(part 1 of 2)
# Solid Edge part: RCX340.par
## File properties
Title: RCX340
Author: psadmin
Template: iso metric part.par
Last saved by: psadmin
Revision: 1
Application: Solid Edge
Document Number: RCX340
Company: YAMAHA
Accuracy: 0,990
NB: RCX340
NN: RCX340
NBSYN: $TYPE.
LINA: RCX340
CATALOG: Yamaha
TYPE: RCX340
SUPPLIER: YAMAHA
ARTICLENO: RCX340
BOMINFO: RCX340
CREATOR: CADENAS GmbH
ID: yamaha:RCX340
CADENASIDSTR: DOCATTR{IDENT{"{$CADENAS_DATA\\23d-libs\\yamaha\\controller\\rcx340\\rcx340.prj},152 {VTYP=3D},{NB=RCX340},{LINA=RCX340},{NN=RCX340},{DATE=25.08.2021 00:08:20},{GEOMDATE=17.03.2021 09:07:48},{VERSION=},{LINEID=20},{WBVAR=},{WBNUMERIC=}  {NB=RCX340},{LINA=RCX340},{KT=DUMMY},{TYPE=RCX340},{VERS=1},{VER=1}"}}
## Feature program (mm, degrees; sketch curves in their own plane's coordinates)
sketch for "ExtrudedProtrusion_1" plane through (0, 0, 0) normal (1, 0, 0) x-axis (0, 1, 0)
extrude "ExtrudedProtrusion_1" add finite 177.5 along -normal  FiniteDepth2 = 177.5 mm
sketch for "ExtrudedCutout_1" #1 plane through (0, 0, -130) normal (0, 0, 1) x-axis (1, 0, 0)
  line (-190, 227) -> (-190, -40)
  line (-190, -40) -> (190, -40)
  line (190, -40) -> (190, 227)
  line (190, 227) -> (-190, 227)
sketch for "ExtrudedCutout_1" #2 plane through (0, 0, -130) normal (0, 0, 1) x-axis (1, 0, 0)
  line (-177.5, 207) -> (-177.5, -12)
  line (-177.5, -12) -> (-174.5, -15)
  line (-174.5, -15) -> (-158.75, -15)
  line (-158.75, -15) -> (-157.75, -14)
  line (-157.75, -14) -> (-157.75, -9)
  arc centre (-155, -9) radius 2.75 from (-157.75, -9) to (-152.25, -9) cw
  line (-152.25, -9) -> (-152.25, -14)
  line (-152.25, -14) -> (-151.25, -15)
  line (-151.25, -15) -> (-3.75, -15)
  line (-3.75, -15) -> (-2.75, -14)
  line (-2.75, -14) -> (-2.75, -9)
  arc centre (0, -9) radius 2.75 from (-2.75, -9) to (2.75, -9) cw
  line (2.75, -9) -> (2.75, -14)
  line (2.75, -14) -> (3.75, -15)
  line (3.75, -15) -> (151.25, -15)
  line (151.25, -15) -> (152.25, -14)
  line (152.25, -14) -> (152.25, -9)
  arc centre (155, -9) radius 2.75 from (152.25, -9) to (157.75, -9) cw
  line (157.75, -9) -> (157.75, -14)
  line (157.75, -14) -> (158.75, -15)
  line (158.75, -15) -> (174.5, -15)
  line (174.5, -15) -> (177.5, -12)
  line (177.5, -12) -> (177.5, 207)
  line (177.5, 207) -> (174.5, 210)
  line (174.5, 210) -> (-174.5, 210)
  line (-174.5, 210) -> (-177.5, 207)
extrude "ExtrudedCutout_1" cut finite 1 along +normal
sketch for "Hole_1" plane through (155, 204, -130) normal (0, 0, 1) x-axis (-1, 0, 0)
  hole centre (0, 0) bore radius 2.75
hole "Hole_1" diameter 5.5 finite
pattern "unnamed Pattern 1" of "Hole_1"
hole "unnamed Hole 1" finite
hole "unnamed Hole 2" finite
sketch for "ExtrudedCutout_2" plane through (0, 195, 0) normal (0, -1, 0) x-axis (1, 0, 0)
  arc centre (37.5, -111) radius 1.5 from (37.5, -112.5) to (37.5, -109.5) cw
  line (37.5, -109.5) -> (54.5, -109.5)
  arc centre (54.5, -111) radius 1.5 from (54.5, -109.5) to (54.5, -112.5) cw
  line (54.5, -112.5) -> (37.5, -112.5)
extrude "ExtrudedCutout_2" cut finite 0.777 along +normal
pattern "unnamed Pattern 2" of "ExtrudedCutout_2"
extrude "unnamed Cutout 1" cut finite 0.777
extrude "unnamed Cutout 2" cut finite 0.777
extrude "unnamed Cutout 3" cut finite 0.777
extrude "unnamed Cutout 4" cut finite 0.777
extrude "unnamed Cutout 5" cut finite 0.777
extrude "unnamed Cutout 6" cut finite 0.777
extrude "unnamed Cutout 7" cut finite 0.777
extrude "unnamed Cutout 8" cut finite 0.777
extrude "unnamed Cutout 9" cut finite 0.777
extrude "unnamed Cutout 10" cut finite 0.777
extrude "unnamed Cutout 11" cut finite 0.777
extrude "unnamed Cutout 12" cut finite 0.777
extrude "unnamed Cutout 13" cut finite 0.777
extrude "unnamed Cutout 14" cut finite 0.777
extrude "unnamed Cutout 15" cut finite 0.777
extrude "unnamed Cutout 16" cut finite 0.777
extrude "unnamed Cutout 17" cut finite 0.777
extrude "unnamed Cutout 18" cut finite 0.777
extrude "unnamed Cutout 19" cut finite 0.777
extrude "unnamed Cutout 20" cut finite 0.777
extrude "unnamed Cutout 21" cut finite 0.777
extrude "unnamed Cutout 22" cut finite 0.777
extrude "unnamed Cutout 23" cut finite 0.777
extrude "unnamed Cutout 24" cut finite 0.777
extrude "unnamed Cutout 25" cut finite 0.777
extrude "unnamed Cutout 26" cut finite 0.777
extrude "unnamed Cutout 27" cut finite 0.777
extrude "unnamed Cutout 28" cut finite 0.777
extrude "unnamed Cutout 29" cut finite 0.777
extrude "unnamed Cutout 30" cut finite 0.777
sketch for "ExtrudedCutout_33" plane through (0, 195, 0) normal (0, -1, 0) x-axis (1, 0, 0)
  arc centre (119, -111) radius 1.5 from (119, -112.5) to (119, -109.5) cw
  line (119, -109.5) -> (136, -109.5)
  arc centre (136, -111) radius 1.5 from (136, -109.5) to (136, -112.5) cw
  line (136, -112.5) -> (119, -112.5)
extrude "ExtrudedCutout_33" cut finite 0.777 along +normal
pattern "unnamed Pattern 3" of "ExtrudedCutout_33"
extrude "unnamed Cutout 31" cut finite 0.777
extrude "unnamed Cutout 32" cut finite 0.777
extrude "unnamed Cutout 33" cut finite 0.777
extrude "unnamed Cutout 34" cut finite 0.777
extrude "unnamed Cutout 35" cut finite 0.777
extrude "unnamed Cutout 36" cut finite 0.777
extrude "unnamed Cutout 37" cut finite 0.777
extrude "unnamed Cutout 38" cut finite 0.777
extrude "unnamed Cutout 39" cut finite 0.777
extrude "unnamed Cutout 40" cut finite 0.777
extrude "unnamed Cutout 41" cut finite 0.777
extrude "unnamed Cutout 42" cut finite 0.777
extrude "unnamed Cutout 43" cut finite 0.777
extrude "unnamed Cutout 44" cut finite 0.777
extrude "unnamed Cutout 45" cut finite 0.777
extrude "unnamed Cutout 46" cut finite 0.777
extrude "unnamed Cutout 47" cut finite 0.777
extrude "unnamed Cutout 48" cut finite 0.777
extrude "unnamed Cutout 49" cut finite 0.777
extrude "unnamed Cutout 50" cut finite 0.777
extrude "unnamed Cutout 51" cut finite 0.777
sketch for "ExtrudedProtrusion_2" plane through (177.5, 0, 0) normal (1, 0, 0) x-axis (0, 1, 0)
  line (168, -110.5) -> (125, -110.5)
  arc centre (125, -112.5) radius 2 from (125, -110.5) to (123, -112.5) ccw
  line (123, -112.5) -> (123, -121.5)
  arc centre (125, -121.5) radius 2 from (123, -121.5) to (125, -123.5) ccw
  line (125, -123.5) -> (168, -123.5)
  arc centre (168, -121.5) radius 2 from (168, -123.5) to (170, -121.5) ccw
  line (170, -121.5) -> (170, -112.5)
  arc centre (168, -112.5) radius 2 from (170, -112.5) to (168, -110.5) ccw
extrude "ExtrudedProtrusion_2" add finite 2 along +normal
sketch for "unnamed RevolvedProtrusion 1" plane through (0, 0, -14.5) normal (0, 0, 1) x-axis (1, 0, 0)
  line (-37.5, -9) -> (-41.2, -9)
  line (-41.2, -9) -> (-41.6, -8.6)
  line (-41.6, -8.6) -> (-41.6, 0)
  line (-41.6, 0) -> (-37.5, 0)
  line (-37.5, 0) -> (-37.5, -9)
revolve "unnamed RevolvedProtrusion 1" add finite 360 deg about sketch line (-37.5, 0) -> (-37.5, -9)
sketch for "unnamed RevolvedProtrusion 2" plane through (0, 0, -38.5) normal (0, 0, 1) x-axis (1, 0, 0)
  line (115.5, 0) -> (119, 0)
  line (119, 0) -> (119, -1)
  line (119, -1) -> (118, -1)
  line (118, -1) -> (118, -2)
  line (118, -2) -> (119.5, -2)
  line (119.5, -2) -> (119.5, -7.5)
  line (119.5, -7.5) -> (119, -8)
  line (119, -8) -> (115.5, -8)
  line (115.5, -8) -> (115.5, 0)
revolve "unnamed RevolvedProtrusion 2" add finite 360 deg about sketch line (115.5, -8) -> (115.5, 0)
sketch for "ExtrudedProtrusion_3" #1 plane through (0, 0, 0) normal (0, 0, 1) x-axis (1, 0, 0)
  line (-177.5, 195) -> (-177.5, 0)
  line (-177.5, 0) -> (177.5, 0)
  line (177.5, 0) -> (177.5, 195)
  line (177.5, 195) -> (-177.5, 195)
sketch for "ExtrudedProtrusion_3" #2 plane through (0, 0, 0) normal (0, 0, 1) x-axis (1, 0, 0)
  line (110.3, 35.2) -> (110.3, 21.8)
  line (110.3, 21.8) -> (123.3, 21.8)
  line (123.3, 21.8) -> (123.3, 35.2)
  line (123.3, 35.2) -> (110.3, 35.2)
sketch for "ExtrudedProtrusion_3" #3 plane through (0, 0, 0) normal (0, 0, 1) x-axis (1, 0, 0)
  line (110.3, 55.7) -> (110.3, 38.3)
  line (110.3, 38.3) -> (125.8, 38.3)
  line (125.8, 38.3) -> (125.8, 55.7)
  line (125.8, 55.7) -> (110.3, 55.7)
sketch for "ExtrudedProtrusion_3" #4 plane through (0, 0, 0) normal (0, 0, 1) x-axis (1, 0, 0)
  line (109.3, 90.2) -> (109.3, 57.8)
  line (109.3, 57.8) -> (125.5, 57.8)
  line (125.5, 57.8) -> (125.5, 90.2)
  line (125.5, 90.2) -> (109.3, 90.2)
sketch for "ExtrudedProtrusion_3" #5 plane through (0, 0, 0) normal (0, 0, 1) x-axis (1, 0, 0)
  line (70.5, 130) -> (70.5, 91)
  line (70.5, 91) -> (84.5, 91)
  line (84.5, 91) -> (84.5, 130)
  line (84.5, 130) -> (70.5, 130)
sketch for "ExtrudedProtrusion_3" #6 plane through (0, 0, 0) normal (0, 0, 1) x-axis (1, 0, 0)
  line (70, 88) -> (70, 37)
  line (70, 37) -> (85, 37)
  line (85, 37) -> (85, 88)
  line (85, 88) -> (70, 88)
sketch for "ExtrudedProtrusion_3" #7 plane through (0, 0, 0) normal (0, 0, 1) x-axis (1, 0, 0)
  line (47.5, 47) -> (47.5, 37)
  line (47.5, 37) -> (61.5, 37)
  line (61.5, 37) -> (61.5, 47)
  line (61.5, 47) -> (47.5, 47)
sketch for "ExtrudedProtrusion_3" #8 plane through (0, 0, 0) normal (0, 0, 1) x-axis (1, 0, 0)
  line (7, 79) -> (7, 34)
  line (7, 34) -> (21, 34)
  line (21, 34) -> (21, 79)
  line (21, 79) -> (7, 79)
sketch for "ExtrudedProtrusion_3" #9 plane through (0, 0, 0) normal (0, 0, 1) x-axis (1, 0, 0)
  line (-115, 79) -> (-115, 34)
  line (-115, 34) -> (-101, 34)
  line (-101, 34) -> (-101, 79)
  line (-101, 79) -> (-115, 79)
sketch for "ExtrudedProtrusion_3" #10 plane through (0, 0, 0) normal (0, 0, 1) x-axis (1, 0, 0)
  line (-169.5, 70.89) -> (-169.5, 38.46)
  line (-169.5, 38.46) -> (-157, 38.46)
  line (-157, 38.46) -> (-157, 70.89)
  line (-157, 70.89) -> (-169.5, 70.89)
extrude "ExtrudedProtrusion_3" add finite 15 along -normal
sketch for "ExtrudedCutout_55" plane through (0, 0, 0) normal (1, 0, 0) x-axis (0, 1, 0)
  line (197.3, 7.7) -> (-2.3, 7.7)
  line (-2.3, 7.7) -> (-2.3, -2.3)
  line (-2.3, -2.3) -> (0, -2.3)
  arc centre (2.3, -2.3) radius 2.3 from (0, -2.3) to (2.3, 0) cw
  line (2.3, 0) -> (192.7, 0)
  arc centre (192.7, -2.3) radius 2.3 from (192.7, 0) to (195, -2.3) cw
  line (195, -2.3) -> (197.3, -2.3)
  line (197.3, -2.3) -> (197.3, 7.7)
extrude "ExtrudedCutout_55" cut finite 177.7 along -normal  FiniteDepth2 = 177.7 mm
sketch for "ExtrudedCutout_56" plane through (-180, 0, 0) normal (1, 0, 0) x-axis (0, 0, -1)
  line (-1, 26.5) -> (-1, -2)
  line (-1, -2) -> (8.8, -2)
  line (8.8, -2) -> (8.8, 0)
  arc centre (8.8, 2.3) radius 2.3 from (8.8, 0) to (6.5, 2.3) cw
  line (6.5, 2.3) -> (6.5, 23.5)
  line (6.5, 23.5) -> (2.3, 23.5)
  arc centre (2.3, 25.8) radius 2.3 from (2.3, 23.5) to (0, 25.8) cw
  line (0, 25.8) -> (0, 26.5)
  line (0, 26.5) -> (-1, 26.5)
extrude "ExtrudedCutout_56" cut finite 281.5 along +normal
sketch for "ExtrudedCutout_57" plane through (0, 0, -6.5) normal (0, 0, 1) x-axis (1, 0, 0)
  line (-129, 20.5) -> (-129, 9.5)
  line (-129, 9.5) -> (-98, 9.5)
  line (-98, 9.5) -> (-98, 20.5)
  line (-98, 20.5) -> (-129, 20.5)
extrude "ExtrudedCutout_57" cut finite 15 along -normal
pattern "unnamed Pattern 4" of "ExtrudedCutout_57"
extrude "unnamed Cutout 52" cut finite 15
extrude "unnamed Cutout 53" cut finite 15
extrude "unnamed Cutout 54" cut finite 15
sketch for "ExtrudedProtrusion_4" #1 plane through (0, 0, -15) normal (0, 0, 1) x-axis (1, 0, 0)
  arc centre (-109.65, 44.7048) radius 1.5 from (-111.15, 44.7048) to (-109.2618, 43.2559) ccw
  line (-109.2618, 43.2559) -> (-105.9618, 44.1402)
  arc centre (-106.35, 45.5891) radius 1.5 from (-105.9618, 44.1402) to (-104.85, 45.5891) ccw
  line (-104.85, 45.5891) -> (-104.85, 67.4109)
  arc centre (-106.35, 67.4109) radius 1.5 from (-104.85, 67.4109) to (-105.9618, 68.8598) ccw
  line (-105.9618, 68.8598) -> (-109.2618, 69.7441)
  arc centre (-109.65, 68.2952) radius 1.5 from (-109.2618, 69.7441) to (-111.15, 68.2952) ccw
  line (-111.15, 68.2952) -> (-111.15, 44.7048)
sketch for "ExtrudedProtrusion_4" #2 plane through (0, 0, -15) normal (0, 0, 1) x-axis (1, 0, 0)
  line (-109.4, 44.7) -> (-106.6, 44.7)
  line (-106.6, 44.7) -> (-106.6, 68.3)
  line (-106.6, 68.3) -> (-109.4, 68.3)
  line (-109.4, 68.3) -> (-109.4, 44.7)
extrude "ExtrudedProtrusion_4" add finite 15 along +normal
sketch for "ExtrudedProtrusion_5" #1 plane through (0, 0, -15) normal (0, 0, 1) x-axis (1, 0, 0)
  line (-112.55, 77.75) -> (-112.55, 35.25)
  line (-112.55, 35.25) -> (-103.45, 35.25)
  line (-103.45, 35.25) -> (-103.45, 77.75)
  line (-103.45, 77.75) -> (-112.55, 77.75)
sketch for "ExtrudedProtrusion_5" #2 plane through (0, 0, -15) normal (0, 0, 1) x-axis (1, 0, 0)
  circle centre (-108, 37.7) radius 1.3
sketch for "ExtrudedProtrusion_5" #3 plane through (0, 0, -15) normal (0, 0, 1) x-axis (1, 0, 0)
  circle centre (-108, 75.31) radius 1.3
extrude "ExtrudedProtrusion_5" add finite 10 along +normal
sketch for "ExtrudedProtrusion_6" #1 plane through (0, 0, -21.5) normal (0, 0, 1) x-axis (1, 0, 0)
  line (-128.12, 11.07) -> (-127.37, 10.32)
  line (-127.37, 10.32) -> (-99.63, 10.32)
  line (-99.63, 10.32) -> (-98.88, 11.07)
  line (-98.88, 11.07) -> (-98.88, 18.92)
  line (-98.88, 18.92) -> (-99.63, 19.67)
  line (-99.63, 19.67) -> (-127.37, 19.67)
  line (-127.37, 19.67) -> (-128.12, 18.92)
  line (-128.12, 18.92) -> (-128.12, 16.12)
  line (-128.12, 16.12) -> (-127.82, 16.12)
  line (-127.82, 16.12) -> (-127.82, 13.87)
  line (-127.82, 13.87) -> (-128.12, 13.87)
  line (-128.12, 13.87) -> (-128.12, 11.07)
sketch for "ExtrudedProtrusion_6" #2 plane through (0, 0, -21.5) normal (0, 0, 1) x-axis (1, 0, 0)
  line (-127.25, 18.4) -> (-127.25, 11.6)
  line (-127.25, 11.6) -> (-99.75, 11.6)
  line (-99.75, 11.6) -> (-99.75, 18.4)
  line (-99.75, 18.4) -> (-127.25, 18.4)
extrude "ExtrudedProtrusion_6" add finite 15 along +normal
pattern "unnamed Pattern 5" of "ExtrudedProtrusion_6"
extrude "unnamed Protrusion 1" add finite 15
extrude "unnamed Protrusion 2" add finite 15
extrude "unnamed Protrusion 3" add finite 15
sketch for "ExtrudedProtrusion_10" plane through (0, 0, -21.5) normal (0, 0, 1) x-axis (1, 0, 0)
  line (-121.97, 15.3) -> (-121.97, 14.7)
  line (-121.97, 14.7) -> (-120.27, 14.7)
  line (-120.27, 14.7) -> (-120.27, 15.3)
  line (-120.27, 15.3) -> (-121.97, 15.3)
extrude "ExtrudedProtrusion_10" add finite 10 along +normal
pattern "unnamed Pattern 6" of "ExtrudedProtrusion_10"
extrude "unnamed Protrusion 4" add finite 10
extrude "unnamed Protrusion 5" add finite 10
extrude "unnamed Protrusion 6" add finite 10
sketch for "ExtrudedProtrusion_14" plane through (0, 0, -21.5) normal (0, 0, 1) x-axis (1, 0, 0)
  line (-60.97, 15.3) -> (-60.97, 14.7)
  line (-60.97, 14.7) -> (-59.27, 14.7)
  line (-59.27, 14.7) -> (-59.27, 15.3)
  line (-59.27, 15.3) -> (-60.97, 15.3)
extrude "ExtrudedProtrusion_14" add finite 10 along +normal
pattern "unnamed Pattern 7" of "ExtrudedProtrusion_14"
extrude "unnamed Protrusion 7" add finite 10
extrude "unnamed Protrusion 8" add finite 10
extrude "unnamed Protrusion 9" add finite 10
sketch for "ExtrudedProtrusion_18" plane through (0, 0, -21.5) normal (0, 0, 1) x-axis (1, 0, 0)
  line (0.03, 15.3) -> (0.03, 14.7)
  line (0.03, 14.7) -> (1.73, 14.7)
  line (1.73, 14.7) -> (1.73, 15.3)
  line (1.73, 15.3) -> (0.03, 15.3)
extrude "ExtrudedProtrusion_18" add finite 10 along +normal
pattern "unnamed Pattern 8" of "ExtrudedProtrusion_18"
extrude "unnamed Protrusion 10" add finite 10
extrude "unnamed Protrusion 11" add finite 10
extrude "unnamed Protrusion 12" add finite 10
sketch for "ExtrudedProtrusion_22" plane through (0, 0, -21.5) normal (0, 0, 1) x-axis (1, 0, 0)
  line (61.03, 15.3) -> (61.03, 14.7)
  line (61.03, 14.7) -> (62.73, 14.7)
  line (62.73, 14.7) -> (62.73, 15.3)
  line (62.73, 15.3) -> (61.03, 15.3)
extrude "ExtrudedProtrusion_22" add finite 10 along +normal
pattern "unnamed Pattern 9" of "ExtrudedProtrusion_22"
extrude "unnamed Protrusion 13" add finite 10
extrude "unnamed Protrusion 14" add finite 10
extrude "unnamed Protrusion 15" add finite 10
sketch for "ExtrudedProtrusion_26" plane through (0, 0, -15) normal (0, 0, 1) x-axis (1, 0, 0)
  line (-111.75, 70.67) -> (-104.25, 70.67)
  line (-104.25, 70.67) -> (-104.25, 73.4)
  line (-104.25, 73.4) -> (-111.75, 73.4)
  line (-111.75, 73.4) -> (-111.75, 70.67)
extrude "ExtrudedProtrusion_26" add finite 15 along +normal
sketch for "ExtrudedProtrusion_27" plane through (0, 0, -15) normal (0, 0, 1) x-axis (1, 0, 0)
  line (-111.75, 39.67) -> (-104.25, 39.67)
  line (-104.25, 39.67) -> (-104.25, 42.4)
  line (-104.25, 42.4) -> (-111.75, 42.4)
  line (-111.75, 42.4) -> (-111.75, 39.67)
extrude "ExtrudedProtrusion_27" add finite 15 along +normal
sketch for "ExtrudedProtrusion_28" #1 plane through (0, 0, -15) normal (0, 0, 1) x-axis (1, 0, 0)
  arc centre (12.35, 44.7048) radius 1.5 from (10.85, 44.7048) to (12.7382, 43.2559) ccw
  line (12.7382, 43.2559) -> (16.0382, 44.1402)
  arc centre (15.65, 45.5891) radius 1.5 from (16.0382, 44.1402) to (17.15, 45.5891) ccw
  line (17.15, 45.5891) -> (17.15, 67.4109)
  arc centre (15.65, 67.4109) radius 1.5 from (17.15, 67.4109) to (16.0382, 68.8598) ccw
  line (16.0382, 68.8598) -> (12.7382, 69.7441)
  arc centre (12.35, 68.2952) radius 1.5 from (12.7382, 69.7441) to (10.85, 68.2952) ccw
  line (10.85, 68.2952) -> (10.85, 44.7048)
sketch for "ExtrudedProtrusion_28" #2 plane through (0, 0, -15) normal (0, 0, 1) x-axis (1, 0, 0)
  line (12.6, 44.7) -> (15.4, 44.7)
  line (15.4, 44.7) -> (15.4, 68.3)
  line (15.4, 68.3) -> (12.6, 68.3)
  line (12.6, 68.3) -> (12.6, 44.7)
extrude "ExtrudedProtrusion_28" add finite 15 along +normal
sketch for "ExtrudedProtrusion_29" #1 plane through (0, 0, -15) normal (0, 0, 1) x-axis (1, 0, 0)
  line (9.45, 77.75) -> (9.45, 35.25)
  line (9.45, 35.25) -> (18.55, 35.25)
  line (18.55, 35.25) -> (18.55, 77.75)
  line (18.55, 77.75) -> (9.45, 77.75)
sketch for "ExtrudedProtrusion_29" #2 plane through (0, 0, -15) normal (0, 0, 1) x-axis (1, 0, 0)
  circle centre (14, 37.7) radius 1.3
sketch for "ExtrudedProtrusion_29" #3 plane through (0, 0, -15) normal (0, 0, 1) x-axis (1, 0, 0)
  circle centre (14, 75.31) radius 1.3
extrude "ExtrudedProtrusion_29" add finite 10 along +normal
sketch for "ExtrudedProtrusion_30" plane through (0, 0, -15) normal (0, 0, 1) x-axis (1, 0, 0)
  line (10.25, 70.67) -> (17.75, 70.67)
  line (17.75, 70.67) -> (17.75, 73.4)
  line (17.75, 73.4) -> (10.25, 73.4)
  line (10.25, 73.4) -> (10.25, 70.67)
extrude "ExtrudedProtrusion_30" add finite 15 along +normal
sketch for "ExtrudedProtrusion_31" plane through (0, 0, -15) normal (0, 0, 1) x-axis (1, 0, 0)
  line (10.25, 39.67) -> (17.75, 39.67)
  line (17.75, 39.67) -> (17.75, 42.4)
  line (17.75, 42.4) -> (10.25, 42.4)
  line (10.25, 42.4) -> (10.25, 39.67)
extrude "ExtrudedProtrusion_31" add finite 15 along +normal
sketch for "ExtrudedProtrusion_32" #1 plane through (0, 0, -15) normal (0, 0, 1) x-axis (1, 0, 0)
  line (48.15, 46.05) -> (48.15, 37)
  line (48.15, 37) -> (56.65, 37)
  line (56.65, 37) -> (56.65, 46.05)
  line (56.65, 46.05) -> (48.15, 46.05)
sketch for "ExtrudedProtrusion_32" #2 plane through (0, 0, -15) normal (0, 0, 1) x-axis (1, 0, 0)
  line (50.15, 45.1) -> (50.15, 37.6)
  line (50.15, 37.6) -> (51.6, 37.6)
  line (51.6, 37.6) -> (51.6, 37.3)
  line (51.6, 37.3) -> (53.4, 37.3)
  line (53.4, 37.3) -> (53.4, 37.6)
  line (53.4, 37.6) -> (54.85, 37.6)
  line (54.85, 37.6) -> (54.85, 45.1)
  line (54.85, 45.1) -> (53.4, 45.1)
  line (53.4, 45.1) -> (53.4, 45.4)
  line (53.4, 45.4) -> (51.6, 45.4)
  line (51.6, 45.4) -> (51.6, 45.1)
  line (51.6, 45.1) -> (50.15, 45.1)
extrude "ExtrudedProtrusion_32" add finite 10 along +normal
sketch for "ExtrudedProtrusion_33" plane through (0, 0, -15) normal (0, 0, 1) x-axis (1, 0, 0)
  line (52, 40.25) -> (52, 39.25)
  line (52, 39.25) -> (53, 39.25)
  line (53, 39.25) -> (53, 40.25)
  line (53, 40.25) -> (52, 40.25)
extrude "ExtrudedProtrusion_33" add finite 10 along +normal
sketch for "ExtrudedProtrusion_34" plane through (0, 0, -15) normal (0, 0, 1) x-axis (1, 0, 0)
  line (52, 43.75) -> (52, 42.75)
  line (52, 42.75) -> (53, 42.75)
  line (53, 42.75) -> (53, 43.75)
  line (53, 43.75) -> (52, 43.75)
extrude "ExtrudedProtrusion_34" add finite 10 along +normal
sketch for "ExtrudedProtrusion_35" #1 plane through (0, 0, -15) normal (0, 0, 1) x-axis (1, 0, 0)
  line (72.2, 87) -> (72.2, 38)
  line (72.2, 38) -> (82.8, 38)
  line (82.8, 38) -> (82.8, 87)
  line (82.8, 87) -> (72.2, 87)
sketch for "ExtrudedProtrusion_35" #2 plane through (0, 0, -15) normal (0, 0, 1) x-axis (1, 0, 0)
  circle centre (75.1, 39.85) radius 1.45
sketch for "ExtrudedProtrusion_35" #3 plane through (0, 0, -15) normal (0, 0, 1) x-axis (1, 0, 0)
  circle centre (75.1, 85.15) radius 1.45
sketch for "ExtrudedProtrusion_35" #4 plane through (0, 0, -15) normal (0, 0, 1) x-axis (1, 0, 0)
  line (72.8, 82.3) -> (72.8, 81.2)
  arc centre (73.8, 81.2) radius 1 from (72.8, 81.2) to (73.8, 80.2) ccw
  line (73.8, 80.2) -> (76.0358, 80.2)
  arc centre (76.0358, 81.2) radius 1 from (76.0358, 80.2) to (76.7429, 80.4929) ccw
  line (76.7429, 80.4929) -> (77.3793, 81.1293)
  arc centre (77.45, 81.0586) radius 0.1 from (77.3793, 81.1293) to (77.5207, 81.1293) cw
  line (77.5207, 81.1293) -> (77.8, 80.85)
  line (77.8, 80.85) -> (77.8, 80.2)
  line (77.8, 80.2) -> (82.1, 80.2)
  arc centre (82.1, 80.4) radius 0.2 from (82.1, 80.2) to (82.3, 80.4) ccw
  line (82.3, 80.4) -> (82.3, 83.1)
  arc centre (82.1, 83.1) radius 0.2 from (82.3, 83.1) to (82.1, 83.3) ccw
  line (82.1, 83.3) -> (77.8, 83.3)
  line (77.8, 83.3) -> (77.8, 82.65)
  line (77.8, 82.65) -> (77.5207, 82.3707)
  arc centre (77.45, 82.4414) radius 0.1 from (77.5207, 82.3707) to (77.3793, 82.3707) cw
  line (77.3793, 82.3707) -> (76.7429, 83.0071)
  arc centre (76.0358, 82.3) radius 1 from (76.7429, 83.0071) to (76.0358, 83.3) ccw
  line (76.0358, 83.3) -> (73.8, 83.3)
  arc centre (73.8, 82.3) radius 1 from (73.8, 83.3) to (72.8, 82.3) ccw
sketch for "ExtrudedProtrusion_35" #5 plane through (0, 0, -15) normal (0, 0, 1) x-axis (1, 0, 0)
  line (72.8, 78.8) -> (72.8, 77.7)
  arc centre (73.8, 77.7) radius 1 from (72.8, 77.7) to (73.8, 76.7) ccw
  line (73.8, 76.7) -> (76.0358, 76.7)
  arc centre (76.0358, 77.7) radius 1 from (76.0358, 76.7) to (76.7429, 76.9929) ccw
  line (76.7429, 76.9929) -> (77.3793, 77.6293)
  arc centre (77.45, 77.5586) radius 0.1 from (77.3793, 77.6293) to (77.5207, 77.6293) cw
  line (77.5207, 77.6293) -> (77.8, 77.35)
  line (77.8, 77.35) -> (77.8, 76.7)
  line (77.8, 76.7) -> (82.1, 76.7)
  arc centre (82.1, 76.9) radius 0.2 from (82.1, 76.7) to (82.3, 76.9) ccw
  line (82.3, 76.9) -> (82.3, 79.6)
  arc centre (82.1, 79.6) radius 0.2 from (82.3, 79.6) to (82.1, 79.8) ccw
  line (82.1, 79.8) -> (77.8, 79.8)
  line (77.8, 79.8) -> (77.8, 79.15)
  line (77.8, 79.15) -> (77.5207, 78.8707)
  arc centre (77.45, 78.9414) radius 0.1 from (77.5207, 78.8707) to (77.3793, 78.8707) cw
  line (77.3793, 78.8707) -> (76.7429, 79.5071)
  arc centre (76.0358, 78.8) radius 1 from (76.7429, 79.5071) to (76.0358, 79.8) ccw
  line (76.0358, 79.8) -> (73.8, 79.8)
  arc centre (73.8, 78.8) radius 1 from (73.8, 79.8) to (72.8, 78.8) ccw
sketch for "ExtrudedProtrusion_35" #6 plane through (0, 0, -15) normal (0, 0, 1) x-axis (1, 0, 0)
  line (72.8, 75.3) -> (72.8, 74.2)
  arc centre (73.8, 74.2) radius 1 from (72.8, 74.2) to (73.8, 73.2) ccw
  line (73.8, 73.2) -> (76.0358, 73.2)
  arc centre (76.0358, 74.2) radius 1 from (76.0358, 73.2) to (76.7429, 73.4929) ccw
  line (0, 0) -> (0, 0)
  line (76.7429, 73.4929) -> (77.3793, 74.1293)
  arc centre (77.45, 74.0586) radius 0.1 from (77.3793, 74.1293) to (77.5207, 74.1293) cw
  line (77.5207, 74.1293) -> (77.8, 73.85)
  line (77.8, 73.85) -> (77.8, 73.2)
  line (77.8, 73.2) -> (82.1, 73.2)
  arc centre (82.1, 73.4) radius 0.2 from (82.1, 73.2) to (82.3, 73.4) ccw
  line (82.3, 73.4) -> (82.3, 76.1)
  arc centre (82.1, 76.1) radius 0.2 from (82.3, 76.1) to (82.1, 76.3) ccw
  line (82.1, 76.3) -> (77.8, 76.3)
  line (77.8, 76.3) -> (77.8, 75.65)
  line (77.8, 75.65) -> (77.5207, 75.3707)
  arc centre (77.45, 75.4414) radius 0.1 from (77.5207, 75.3707) to (77.3793, 75.3707) cw
  line (77.3793, 75.3707) -> (76.7429, 76.0071)
  arc centre (76.0358, 75.3) radius 1 from (76.7429, 76.0071) to (76.0358, 76.3) ccw
  line (76.0358, 76.3) -> (73.8, 76.3)
  arc centre (73.8, 75.3) radius 1 from (73.8, 76.3) to (72.8, 75.3) ccw
sketch for "ExtrudedProtrusion_35" #7 plane through (0, 0, -15) normal (0, 0, 1) x-axis (1, 0, 0)
  line (72.8, 71.8) -> (72.8, 70.7)
  arc centre (73.8, 70.7) radius 1 from (72.8, 70.7) to (73.8, 69.7) ccw
  line (73.8, 69.7) -> (76.0358, 69.7)
  arc centre (76.0358, 70.7) radius 1 from (76.0358, 69.7) to (76.7429, 69.9929) ccw
  line (76.7429, 69.9929) -> (77.3793, 70.6293)
  arc centre (77.45, 70.5586) radius 0.1 from (77.3793, 70.6293) to (77.5207, 70.6293) cw
  line (77.5207, 70.6293) -> (77.8, 70.35)
  line (77.8, 70.35) -> (77.8, 69.7)
  line (77.8, 69.7) -> (82.1, 69.7)
  arc centre (82.1, 69.9) radius 0.2 from (82.1, 69.7) to (82.3, 69.9) ccw
  line (82.3, 69.9) -> (82.3, 72.6)
  arc centre (82.1, 72.6) radius 0.2 from (82.3, 72.6) to (82.1, 72.8) ccw
  line (82.1, 72.8) -> (77.8, 72.8)
  line (77.8, 72.8) -> (77.8, 72.15)
  line (77.8, 72.15) -> (77.5207, 71.8707)
  arc centre (77.45, 71.9414) radius 0.1 from (77.5207, 71.8707) to (77.3793, 71.8707) cw
  line (77.3793, 71.8707) -> (76.7429, 72.5071)
  arc centre (76.0358, 71.8) radius 1 from (76.7429, 72.5071) to (76.0358, 72.8) ccw
  line (76.0358, 72.8) -> (73.8, 72.8)
  arc centre (73.8, 71.8) radius 1 from (73.8, 72.8) to (72.8, 71.8) ccw
sketch for "ExtrudedProtrusion_35" #8 plane through (0, 0, -15) normal (0, 0, 1) x-axis (1, 0, 0)
  line (72.8, 68.3) -> (72.8, 67.2)
  arc centre (73.8, 67.2) radius 1 from (72.8, 67.2) to (73.8, 66.2) ccw
  line (73.8, 66.2) -> (76.0358, 66.2)
  arc centre (76.0358, 67.2) radius 1 from (76.0358, 66.2) to (76.7429, 66.4929) ccw
  line (76.7429, 66.4929) -> (77.3793, 67.1293)
  arc centre (77.45, 67.0586) radius 0.1 from (77.3793, 67.1293) to (77.5207, 67.1293) cw
  line (77.5207, 67.1293) -> (77.8, 66.85)
  line (77.8, 66.85) -> (77.8, 66.2)
  line (77.8, 66.2) -> (82.1, 66.2)
  arc centre (82.1, 66.4) radius 0.2 from (82.1, 66.2) to (82.3, 66.4) ccw
  line (82.3, 66.4) -> (82.3, 69.1)
  arc centre (82.1, 69.1) radius 0.2 from (82.3, 69.1) to (82.1, 69.3) ccw
  line (82.1, 69.3) -> (77.8, 69.3)
  line (77.8, 69.3) -> (77.8, 68.65)
  line (77.8, 68.65) -> (77.5207, 68.3707)
  arc centre (77.45, 68.4414) radius 0.1 from (77.5207, 68.3707) to (77.3793, 68.3707) cw
  line (77.3793, 68.3707) -> (76.7429, 69.0071)
  arc centre (76.0358, 68.3) radius 1 from (76.7429, 69.0071) to (76.0358, 69.3) ccw
  line (76.0358, 69.3) -> (73.8, 69.3)
  arc centre (73.8, 68.3) radius 1 from (73.8, 69.3) to (72.8, 68.3) ccw
sketch for "ExtrudedProtrusion_35" #9 plane through (0, 0, -15) normal (0, 0, 1) x-axis (1, 0, 0)
  line (72.8, 64.8) -> (72.8, 63.7)
  arc centre (73.8, 63.7) radius 1 from (72.8, 63.7) to (73.8, 62.7) ccw
  line (73.8, 62.7) -> (76.0358, 62.7)
  arc centre (76.0358, 63.7) radius 1 from (76.0358, 62.7) to (76.7429, 62.9929) ccw
  line (76.7429, 62.9929) -> (77.3793, 63.6293)
  arc centre (77.45, 63.5586) radius 0.1 from (77.3793, 63.6293) to (77.5207, 63.6293) cw
  line (77.5207, 63.6293) -> (77.8, 63.35)
  line (77.8, 63.35) -> (77.8, 62.7)
  line (77.8, 62.7) -> (82.1, 62.7)
  arc centre (82.1, 62.9) radius 0.2 from (82.1, 62.7) to (82.3, 62.9) ccw
  line (82.3, 62.9) -> (82.3, 65.6)
  arc centre (82.1, 65.6) radius 0.2 from (82.3, 65.6) to (82.1, 65.8) ccw
  line (82.1, 65.8) -> (77.8, 65.8)
  line (77.8, 65.8) -> (77.8, 65.15)
  line (77.8, 65.15) -> (77.5207, 64.8707)
  arc centre (77.45, 64.9414) radius 0.1 from (77.5207, 64.8707) to (77.3793, 64.8707) cw
  line (77.3793, 64.8707) -> (76.7429, 65.5071)
  arc centre (76.0358, 64.8) radius 1 from (76.7429, 65.5071) to (76.0358, 65.8) ccw
  line (76.0358, 65.8) -> (73.8, 65.8)
  arc centre (73.8, 64.8) radius 1 from (73.8, 65.8) to (72.8, 64.8) ccw
sketch for "ExtrudedProtrusion_35" #10 plane through (0, 0, -15) normal (0, 0, 1) x-axis (1, 0, 0)
  line (72.8, 61.3) -> (72.8, 60.2)
  arc centre (73.8, 60.2) radius 1 from (72.8, 60.2) to (73.8, 59.2) ccw
  line (73.8, 59.2) -> (76.0358, 59.2)
  arc centre (76.0358, 60.2) radius 1 from (76.0358, 59.2) to (76.7429, 59.4929) ccw
  line (76.7429, 59.4929) -> (77.3793, 60.1293)
  arc centre (77.45, 60.0586) radius 0.1 from (77.3793, 60.1293) to (77.5207, 60.1293) cw
  line (77.5207, 60.1293) -> (77.8, 59.85)
  line (77.8, 59.85) -> (77.8, 59.2)
  line (77.8, 59.2) -> (82.1, 59.2)
  arc centre (82.1, 59.4) radius 0.2 from (82.1, 59.2) to (82.3, 59.4) ccw
  line (82.3, 59.4) -> (82.3, 62.1)
  arc centre (82.1, 62.1) radius 0.2 from (82.3, 62.1) to (82.1, 62.3) ccw
  line (82.1, 62.3) -> (77.8, 62.3)
  line (77.8, 62.3) -> (77.8, 61.65)
  line (77.8, 61.65) -> (77.5207, 61.3707)
  arc centre (77.45, 61.4414) radius 0.1 from (77.5207, 61.3707) to (77.3793, 61.3707) cw
  line (77.3793, 61.3707) -> (76.7429, 62.0071)
  arc centre (76.0358, 61.3) radius 1 from (76.7429, 62.0071) to (76.0358, 62.3) ccw
  line (76.0358, 62.3) -> (73.8, 62.3)
  arc centre (73.8, 61.3) radius 1 from (73.8, 62.3) to (72.8, 61.3) ccw
sketch for "ExtrudedProtrusion_35" #11 plane through (0, 0, -15) normal (0, 0, 1) x-axis (1, 0, 0)
  line (72.8, 57.8) -> (72.8, 56.7)
  arc centre (73.8, 56.7) radius 1 from (72.8, 56.7) to (73.8, 55.7) ccw
  line (73.8, 55.7) -> (76.0358, 55.7)
  arc centre (76.0358, 56.7) radius 1 from (76.0358, 55.7) to (76.7429, 55.9929) ccw
  line (76.7429, 55.9929) -> (77.3793, 56.6293)
  arc centre (77.45, 56.5586) radius 0.1 from (77.3793, 56.6293) to (77.5207, 56.6293) cw
  line (77.5207, 56.6293) -> (77.8, 56.35)
  line (77.8, 56.35) -> (77.8, 55.7)
  line (77.8, 55.7) -> (82.1, 55.7)
  arc centre (82.1, 55.9) radius 0.2 from (82.1, 55.7) to (82.3, 55.9) ccw
  line (82.3, 55.9) -> (82.3, 58.6)
  arc centre (82.1, 58.6) radius 0.2 from (82.3, 58.6) to (82.1, 58.8) ccw
  line (82.1, 58.8) -> (77.8, 58.8)
  line (77.8, 58.8) -> (77.8, 58.15)
  line (77.8, 58.15) -> (77.5207, 57.8707)
  arc centre (77.45, 57.9414) radius 0.1 from (77.5207, 57.8707) to (77.3793, 57.8707) cw
  line (77.3793, 57.8707) -> (76.7429, 58.5071)
  arc centre (76.0358, 57.8) radius 1 from (76.7429, 58.5071) to (76.0358, 58.8) ccw
  line (76.0358, 58.8) -> (73.8, 58.8)
  arc centre (73.8, 57.8) radius 1 from (73.8, 58.8) to (72.8, 57.8) ccw
sketch for "ExtrudedProtrusion_35" #12 plane through (0, 0, -15) normal (0, 0, 1) x-axis (1, 0, 0)
  line (72.8, 54.3) -> (72.8, 53.2)
  arc centre (73.8, 53.2) radius 1 from (72.8, 53.2) to (73.8, 52.2) ccw
  line (73.8, 52.2) -> (76.0358, 52.2)
  arc centre (76.0358, 53.2) radius 1 from (76.0358, 52.2) to (76.7429, 52.4929) ccw
  line (76.7429, 52.4929) -> (77.3793, 53.1293)
  arc centre (77.45, 53.0586) radius 0.1 from (77.3793, 53.1293) to (77.5207, 53.1293) cw
  line (77.5207, 53.1293) -> (77.8, 52.85)
  line (77.8, 52.85) -> (77.8, 52.2)
  line (77.8, 52.2) -> (82.1, 52.2)
  arc centre (82.1, 52.4) radius 0.2 from (82.1, 52.2) to (82.3, 52.4) ccw
  line (82.3, 52.4) -> (82.3, 55.1)
  arc centre (82.1, 55.1) radius 0.2 from (82.3, 55.1) to (82.1, 55.3) ccw
  line (82.1, 55.3) -> (77.8, 55.3)
  line (77.8, 55.3) -> (77.8, 54.65)
  line (77.8, 54.65) -> (77.5207, 54.3707)
  arc centre (77.45, 54.4414) radius 0.1 from (77.5207, 54.3707) to (77.3793, 54.3707) cw
  line (77.3793, 54.3707) -> (76.7429, 55.0071)
  arc centre (76.0358, 54.3) radius 1 from (76.7429, 55.0071) to (76.0358, 55.3) ccw
  line (76.0358, 55.3) -> (73.8, 55.3)
  arc centre (73.8, 54.3) radius 1 from (73.8, 55.3) to (72.8, 54.3) ccw
sketch for "ExtrudedProtrusion_35" #13 plane through (0, 0, -15) normal (0, 0, 1) x-axis (1, 0, 0)
  line (72.8, 50.8) -> (72.8, 49.7)
  arc centre (73.8, 49.7) radius 1 from (72.8, 49.7) to (73.8, 48.7) ccw
  line (73.8, 48.7) -> (76.0358, 48.7)
  arc centre (76.0358, 49.7) radius 1 from (76.0358, 48.7) to (76.7429, 48.9929) ccw
  line (76.7429, 48.9929) -> (77.3793, 49.6293)
  arc centre (77.45, 49.5586) radius 0.1 from (77.3793, 49.6293) to (77.5207, 49.6293) cw
  line (77.5207, 49.6293) -> (77.8, 49.35)
  line (77.8, 49.35) -> (77.8, 48.7)
  line (77.8, 48.7) -> (82.1, 48.7)
  arc centre (82.1, 48.9) radius 0.2 from (82.1, 48.7) to (82.3, 48.9) ccw
  line (82.3, 48.9) -> (82.3, 51.6)
  arc centre (82.1, 51.6) radius 0.2 from (82.3, 51.6) to (82.1, 51.8) ccw
  line (82.1, 51.8) -> (77.8, 51.8)
  line (77.8, 51.8) -> (77.8, 51.15)
  line (77.8, 51.15) -> (77.5207, 50.8707)
  arc centre (77.45, 50.9414) radius 0.1 from (77.5207, 50.8707) to (77.3793, 50.8707) cw
  line (77.3793, 50.8707) -> (76.7429, 51.5071)
  arc centre (76.0358, 50.8) radius 1 from (76.7429, 51.5071) to (76.0358, 51.8) ccw
  line (76.0358, 51.8) -> (73.8, 51.8)
  arc centre (73.8, 50.8) radius 1 from (73.8, 51.8) to (72.8, 50.8) ccw
sketch for "ExtrudedProtrusion_35" #14 plane through (0, 0, -15) normal (0, 0, 1) x-axis (1, 0, 0)
  line (72.8, 47.3) -> (72.8, 46.2)
  arc centre (73.8, 46.2) radius 1 from (72.8, 46.2) to (73.8, 45.2) ccw
  line (73.8, 45.2) -> (76.0358, 45.2)
  arc centre (76.0358, 46.2) radius 1 from (76.0358, 45.2) to (76.7429, 45.4929) ccw
  line (76.7429, 45.4929) -> (77.3793, 46.1293)
  arc centre (77.45, 46.0586) radius 0.1 from (77.3793, 46.1293) to (77.5207, 46.1293) cw
  line (77.5207, 46.1293) -> (77.8, 45.85)
  line (77.8, 45.85) -> (77.8, 45.2)
  line (77.8, 45.2) -> (82.1, 45.2)
  arc centre (82.1, 45.4) radius 0.2 from (82.1, 45.2) to (82.3, 45.4) ccw
  line (82.3, 45.4) -> (82.3, 48.1)
  arc centre (82.1, 48.1) radius 0.2 from (82.3, 48.1) to (82.1, 48.3) ccw
  line (82.1, 48.3) -> (77.8, 48.3)
  line (77.8, 48.3) -> (77.8, 47.65)
  line (77.8, 47.65) -> (77.5207, 47.3707)
  arc centre (77.45, 47.4414) radius 0.1 from (77.5207, 47.3707) to (77.3793, 47.3707) cw
  line (77.3793, 47.3707) -> (76.7429, 48.0071)
  arc centre (76.0358, 47.3) radius 1 from (76.7429, 48.0071) to (76.0358, 48.3) ccw
  line (76.0358, 48.3) -> (73.8, 48.3)
  arc centre (73.8, 47.3) radius 1 from (73.8, 48.3) to (72.8, 47.3) ccw
sketch for "ExtrudedProtrusion_35" #15 plane through (0, 0, -15) normal (0, 0, 1) x-axis (1, 0, 0)
  line (72.8, 43.8) -> (72.8, 42.7)
  arc centre (73.8, 42.7) radius 1 from (72.8, 42.7) to (73.8, 41.7) ccw
  line (73.8, 41.7) -> (76.0358, 41.7)
  arc centre (76.0358, 42.7) radius 1 from (76.0358, 41.7) to (76.7429, 41.9929) ccw
  line (76.7429, 41.9929) -> (77.3793, 42.6293)
  arc centre (77.45, 42.5586) radius 0.1 from (77.3793, 42.6293) to (77.5207, 42.6293) cw
  line (77.5207, 42.6293) -> (77.8, 42.35)
  line (77.8, 42.35) -> (77.8, 41.7)
  line (77.8, 41.7) -> (82.1, 41.7)
  arc centre (82.1, 41.9) radius 0.2 from (82.1, 41.7) to (82.3, 41.9) ccw
  line (82.3, 41.9) -> (82.3, 44.6)
  arc centre (82.1, 44.6) radius 0.2 from (82.3, 44.6) to (82.1, 44.8) ccw
  line (82.1, 44.8) -> (77.8, 44.8)
  line (77.8, 44.8) -> (77.8, 44.15)
  line (77.8, 44.15) -> (77.5207, 43.8707)
  arc centre (77.45, 43.9414) radius 0.1 from (77.5207, 43.8707) to (77.3793, 43.8707) cw
  line (77.3793, 43.8707) -> (76.7429, 44.5071)
  arc centre (76.0358, 43.8) radius 1 from (76.7429, 44.5071) to (76.0358, 44.8) ccw
  line (76.0358, 44.8) -> (73.8, 44.8)
  arc centre (73.8, 43.8) radius 1 from (73.8, 44.8) to (72.8, 43.8) ccw
extrude "ExtrudedProtrusion_35" add finite 15 along +normal
sketch for "ExtrudedCutout_61" plane through (0, 0, -15) normal (0, 0, 1) x-axis (1, 0, 0)
  line (79.75, 80.2) -> (79.75, 44.8)
  line (79.75, 44.8) -> (80.75, 44.8)
  line (80.75, 44.8) -> (80.75, 80.2)
  line (80.75, 80.2) -> (79.75, 80.2)
extrude "ExtrudedCutout_61" cut finite 15 along +normal
sketch for "ExtrudedCutout_62" plane through (0, 0, -15) normal (0, 0, 1) x-axis (1, 0, 0)
  line (74.25, 80.2) -> (74.25, 44.8)
  line (74.25, 44.8) -> (75.25, 44.8)
  line (75.25, 44.8) -> (75.25, 80.2)
  line (75.25, 80.2) -> (74.25, 80.2)
extrude "ExtrudedCutout_62" cut finite 15 along +normal
sketch for "ExtrudedProtrusion_36" #1 plane through (0, 0, -15) normal (0, 0, 1) x-axis (1, 0, 0)
  line (74.35, 118.2109) -> (74.35, 102.7891)
  arc centre (75.85, 102.7891) radius 1.5 from (74.35, 102.7891) to (75.4618, 101.3402) ccw
  line (75.4618, 101.3402) -> (78.7618, 100.4559)
  arc centre (79.15, 101.9048) radius 1.5 from (78.7618, 100.4559) to (80.65, 101.9048) ccw
  line (80.65, 101.9048) -> (80.65, 119.0952)
  arc centre (79.15, 119.0952) radius 1.5 from (80.65, 119.0952) to (78.7618, 120.5441) ccw
  line (78.7618, 120.5441) -> (75.4618, 119.6598)
  arc centre (75.85, 118.2109) radius 1.5 from (75.4618, 119.6598) to (74.35, 118.2109) ccw
sketch for "ExtrudedProtrusion_36" #2 plane through (0, 0, -15) normal (0, 0, 1) x-axis (1, 0, 0)
  line (76.1, 119.1) -> (76.1, 101.9)
  line (76.1, 101.9) -> (78.9, 101.9)
  line (78.9, 101.9) -> (78.9, 119.1)
  line (78.9, 119.1) -> (76.1, 119.1)
extrude "ExtrudedProtrusion_36" add finite 15 along +normal
sketch for "ExtrudedProtrusion_37" #1 plane through (0, 0, -15) normal (0, 0, 1) x-axis (1, 0, 0)
  line (72.95, 128.6) -> (72.95, 92.4)
  line (72.95, 92.4) -> (82.05, 92.4)
  line (82.05, 92.4) -> (82.05, 128.6)
  line (82.05, 128.6) -> (72.95, 128.6)
sketch for "ExtrudedProtrusion_37" #2 plane through (0, 0, -15) normal (0, 0, 1) x-axis (1, 0, 0)
  circle centre (77.5, 126.13) radius 1.3
sketch for "ExtrudedProtrusion_37" #3 plane through (0, 0, -15) normal (0, 0, 1) x-axis (1, 0, 0)
  circle centre (77.5, 94.87) radius 1.3
extrude "ExtrudedProtrusion_37" add finite 10 along +normal
sketch for "ExtrudedProtrusion_38" plane through (0, 0, -15) normal (0, 0, 1) x-axis (1, 0, 0)
  line (73.75, 124.23) -> (73.75, 121.43)
  line (73.75, 121.43) -> (81.25, 121.43)
  line (81.25, 121.43) -> (81.25, 124.23)
  line (81.25, 124.23) -> (73.75, 124.23)
extrude "ExtrudedProtrusion_38" add finite 15 along +normal
sketch for "ExtrudedProtrusion_39" plane through (0, 0, -15) normal (0, 0, 1) x-axis (1, 0, 0)
  line (73.75, 99.58) -> (73.75, 96.78)
  line (73.75, 96.78) -> (81.25, 96.78)
  line (81.25, 96.78) -> (81.25, 99.58)
  line (81.25, 99.58) -> (73.75, 99.58)
extrude "ExtrudedProtrusion_39" add finite 15 along +normal
sketch for "ExtrudedProtrusion_40" #1 plane through (0, 0, -15) normal (0, 0, 1) x-axis (1, 0, 0)
  line (111.1, 34.52) -> (111.1, 22.48)
  line (111.1, 22.48) -> (121.85, 22.48)
  arc centre (121.85, 22.73) radius 0.25 from (121.85, 22.48) to (122.1, 22.73) ccw
  line (122.1, 22.73) -> (122.1, 34.27)
  arc centre (121.85, 34.27) radius 0.25 from (122.1, 34.27) to (121.85, 34.52) ccw
  line (121.85, 34.52) -> (111.1, 34.52)
sketch for "ExtrudedProtrusion_40" #2 plane through (0, 0, -15) normal (0, 0, 1) x-axis (1, 0, 0)
  line (112.9, 32.72) -> (112.9, 24.27)
  line (112.9, 24.27) -> (119.2, 24.27)
  line (119.2, 24.27) -> (120.68, 25.75)
  line (120.68, 25.75) -> (120.68, 31.24)
  line (120.68, 31.24) -> (119.2, 32.72)
  line (119.2, 32.72) -> (112.9, 32.72)
extrude "ExtrudedProtrusion_40" add finite 15 along +normal
sketch for "ExtrudedProtrusion_41" plane through (0, 0, -15) normal (0, 0, 1) x-axis (1, 0, 0)
  line (115.24, 31.25) -> (115.24, 25.75)
  line (115.24, 25.75) -> (118.34, 25.75)
  line (118.34, 25.75) -> (118.34, 31.25)
  line (118.34, 31.25) -> (115.24, 31.25)
extrude "ExtrudedProtrusion_41" add finite 15 along +normal
sketch for "ExtrudedProtrusion_42" #1 plane through (0, 0, -15) normal (0, 0, 1) x-axis (1, 0, 0)
  line (111.1, 55.13) -> (111.1, 38.87)
  line (111.1, 38.87) -> (124.94, 38.87)
  line (124.94, 38.87) -> (124.94, 55.13)
  line (124.94, 55.13) -> (111.1, 55.13)
sketch for "ExtrudedProtrusion_42" #2 plane through (0, 0, -15) normal (0, 0, 1) x-axis (1, 0, 0)
  line (111.6, 49) -> (111.6, 45)
  line (111.6, 45) -> (112.6, 45)
  line (112.6, 45) -> (112.6, 44)
  line (112.6, 44) -> (114.44, 44)
  line (114.44, 44) -> (114.44, 41)
  line (114.44, 41) -> (121.44, 41)
  line (121.44, 41) -> (121.44, 43.15)
  line (121.44, 43.15) -> (122.44, 43.15)
  line (122.44, 43.15) -> (122.44, 43.85)
  line (122.44, 43.85) -> (121.44, 43.85)
  line (121.44, 43.85) -> (121.44, 44.15)
  line (121.44, 44.15) -> (122.44, 44.15)
  line (122.44, 44.15) -> (122.44, 44.85)
  line (122.44, 44.85) -> (121.44, 44.85)
  line (121.44, 44.85) -> (121.44, 45.15)
  line (121.44, 45.15) -> (122.44, 45.15)
  line (122.44, 45.15) -> (122.44, 45.85)
  line (122.44, 45.85) -> (121.44, 45.85)
  line (121.44, 45.85) -> (121.44, 46.15)
  line (121.44, 46.15) -> (122.44, 46.15)
  line (122.44, 46.15) -> (122.44, 46.85)
  line (122.44, 46.85) -> (121.44, 46.85)
  line (121.44, 46.85) -> (121.44, 47.15)
  line (121.44, 47.15) -> (122.44, 47.15)
  line (122.44, 47.15) -> (122.44, 47.85)
  line (122.44, 47.85) -> (121.44, 47.85)
  line (121.44, 47.85) -> (121.44, 48.15)
  line (121.44, 48.15) -> (122.44, 48.15)
  line (122.44, 48.15) -> (122.44, 48.85)
  line (122.44, 48.85) -> (121.44, 48.85)
  line (121.44, 48.85) -> (121.44, 49.15)
  line (121.44, 49.15) -> (122.44, 49.15)
  line (122.44, 49.15) -> (122.44, 49.85)
  line (122.44, 49.85) -> (121.44, 49.85)
  line (121.44, 49.85) -> (121.44, 50.15)
  line (121.44, 50.15) -> (122.44, 50.15)
  line (122.44, 50.15) -> (122.44, 50.85)
  line (122.44, 50.85) -> (121.44, 50.85)
  line (121.44, 50.85) -> (121.44, 53)
  line (121.44, 53) -> (114.44, 53)
  line (114.44, 53) -> (114.44, 50)
  line (114.44, 50) -> (112.6, 50)
  line (112.6, 50) -> (112.6, 49)
  line (112.6, 49) -> (111.6, 49)
extrude "ExtrudedProtrusion_42" add finite 15 along +normal
sketch for "ExtrudedProtrusion_43" #1 plane through (0, 0, -15) normal (0, 0, 1) x-axis (1, 0, 0)
  line (113.4, 79.1393) -> (113.4, 68.8607)
  arc centre (115.9, 68.8607) radius 2.5 from (113.4, 68.8607) to (115.4659, 66.3987) ccw
  line (115.4659, 66.3987) -> (118.3659, 65.8874)
  arc centre (118.8, 68.3494) radius 2.5 from (118.3659, 65.8874) to (121.3, 68.3494) ccw
  line (121.3, 68.3494) -> (121.3, 79.6506)
  arc centre (118.8, 79.6506) radius 2.5 from (121.3, 79.6506) to (118.3659, 82.1126) ccw
  line (118.3659, 82.1126) -> (115.4659, 81.6013)
  arc centre (115.9, 79.1393) radius 2.5 from (115.4659, 81.6013) to (113.4, 79.1393) ccw
sketch for "ExtrudedProtrusion_43" #2 plane through (0, 0, -15) normal (0, 0, 1) x-axis (1, 0, 0)
  circle centre (118.77, 68.51) radius 0.5
sketch for "ExtrudedProtrusion_43" #3 plane through (0, 0, -15) normal (0, 0, 1) x-axis (1, 0, 0)
  circle centre (118.77, 71.26) radius 0.5
sketch for "ExtrudedProtrusion_43" #4 plane through (0, 0, -15) normal (0, 0, 1) x-axis (1, 0, 0)
  circle centre (118.77, 74.01) radius 0.5
sketch for "ExtrudedProtrusion_43" #5 plane through (0, 0, -15) normal (0, 0, 1) x-axis (1, 0, 0)
  circle centre (118.77, 76.76) radius 0.5
sketch for "ExtrudedProtrusion_43" #6 plane through (0, 0, -15) normal (0, 0, 1) x-axis (1, 0, 0)
  circle centre (118.77, 79.51) radius 0.5
sketch for "ExtrudedProtrusion_43" #7 plane through (0, 0, -15) normal (0, 0, 1) x-axis (1, 0, 0)
  circle centre (115.93, 69.89) radius 0.5
sketch for "ExtrudedProtrusion_43" #8 plane through (0, 0, -15) normal (0, 0, 1) x-axis (1, 0, 0)
  circle centre (115.93, 72.63) radius 0.5
sketch for "ExtrudedProtrusion_43" #9 plane through (0, 0, -15) normal (0, 0, 1) x-axis (1, 0, 0)
  circle centre (115.93, 75.37) radius 0.5
sketch for "ExtrudedProtrusion_43" #10 plane through (0, 0, -15) normal (0, 0, 1) x-axis (1, 0, 0)
  circle centre (115.93, 78.11) radius 0.5
extrude "ExtrudedProtrusion_43" add finite 15 along +normal
sketch for "ExtrudedProtrusion_44" plane through (0, 0, -15) normal (0, 0, 1) x-axis (1, 0, 0)
  line (111.1, 89.4) -> (111.1, 58.6)
  line (111.1, 58.6) -> (121.8, 58.6)
  arc centre (121.8, 60.4) radius 1.8 from (121.8, 58.6) to (123.6, 60.4) ccw
  line (123.6, 60.4) -> (123.6, 87.6)
  arc centre (121.8, 87.6) radius 1.8 from (123.6, 87.6) to (121.8, 89.4) ccw
  line (121.8, 89.4) -> (111.1, 89.4)
extrude "ExtrudedProtrusion_44" add finite 10 along +normal
sketch for "ExtrudedProtrusion_45" #1 plane through (0, 0, -15) normal (0, 0, 1) x-axis (1, 0, 0)
  line (114.4632, 86.5) -> (115.9066, 84)
  line (115.9066, 84) -> (118.7934, 84)
  line (118.7934, 84) -> (120.2368, 86.5)
  line (120.2368, 86.5) -> (118.7934, 89)
  line (118.7934, 89) -> (115.9066, 89)
  line (115.9066, 89) -> (114.4632, 86.5)
sketch for "ExtrudedProtrusion_45" #2 plane through (0, 0, -15) normal (0, 0, 1) x-axis (1, 0, 0)
  circle centre (117.35, 86.5) radius 1.41
extrude "ExtrudedProtrusion_45" add finite 15 along +normal
sketch for "ExtrudedProtrusion_46" #1 plane through (0, 0, -15) normal (0, 0, 1) x-axis (1, 0, 0)
  line (114.4632, 61.51) -> (115.9066, 59.01)
  line (115.9066, 59.01) -> (118.7934, 59.01)
  line (118.7934, 59.01) -> (120.2368, 61.51)
  line (120.2368, 61.51) -> (118.7934, 64.01)
  line (118.7934, 64.01) -> (115.9066, 64.01)
  line (115.9066, 64.01) -> (114.4632, 61.51)
sketch for "ExtrudedProtrusion_46" #2 plane through (0, 0, -15) normal (0, 0, 1) x-axis (1, 0, 0)
  circle centre (117.35, 61.51) radius 1.41
extrude "ExtrudedProtrusion_46" add finite 15 along +normal
sketch for "ExtrudedCutout_63" #1 plane through (0, 0, 0) normal (0, 0, 1) x-axis (1, 0, 0)
  line (129.5, 92.5) -> (129.5, 18.5)
  line (129.5, 18.5) -> (170.7, 18.5)
  line (170.7, 18.5) -> (170.7, 92.5)
  line (170.7, 92.5) -> (129.5, 92.5)
sketch for "ExtrudedCutout_63" #2 plane through (0, 0, 0) normal (0, 0, 1) x-axis (1, 0, 0)
  line (150.2, 92.4) -> (150.2, 18.6)
  line (150.2, 18.6) -> (170.6, 18.6)
  line (170.6, 18.6) -> (170.6, 92.4)
  line (170.6, 92.4) -> (150.2, 92.4)
sketch for "ExtrudedCutout_63" #3 plane through (0, 0, 0) normal (0, 0, 1) x-axis (1, 0, 0)
  line (129.6, 18.6) -> (150, 18.6)
  line (150, 18.6) -> (150, 92.4)
  line (150, 92.4) -> (129.6, 92.4)
  line (129.6, 92.4) -> (129.6, 18.6)
extrude "ExtrudedCutout_63" cut finite 0.1 along -normal
sketch for "ExtrudedProtrusion_47" plane through (0, 0, 0) normal (0, 0, 1) x-axis (1, 0, 0)
  line (105.5, 11.5) -> (105.5, 3.5)
  arc centre (106.5, 3.5) radius 1 from (105.5, 3.5) to (106.5, 2.5) ccw
  line (106.5, 2.5) -> (128.5, 2.5)
  arc centre (128.5, 3.5) radius 1 from (128.5, 2.5) to (129.5, 3.5) ccw
  line (129.5, 3.5) -> (129.5, 11.5)
  arc centre (128.5, 11.5) radius 1 from (129.5, 11.5) to (128.5, 12.5) ccw
  line (128.5, 12.5) -> (106.5, 12.5)
  arc centre (106.5, 11.5) radius 1 from (106.5, 12.5) to (105.5, 11.5) ccw
extrude "ExtrudedProtrusion_47" add finite 0.1 along +normal
sketch for "ExtrudedCutout_64" #1 plane through (0, 0, 0) normal (0, 0, 1) x-axis (1, 0, 0)
  line (129.5, 183.5) -> (129.5, 109.5)
  line (129.5, 109.5) -> (170.7, 109.5)
  line (170.7, 109.5) -> (170.7, 183.5)
  line (170.7, 183.5) -> (129.5, 183.5)
sketch for "ExtrudedCutout_64" #2 plane through (0, 0, 0) normal (0, 0, 1) x-axis (1, 0, 0)
  line (150.2, 183.4) -> (150.2, 109.6)
  line (150.2, 109.6) -> (170.6, 109.6)
  line (170.6, 109.6) -> (170.6, 183.4)
  line (170.6, 183.4) -> (150.2, 183.4)
sketch for "ExtrudedCutout_64" #3 plane through (0, 0, 0) normal (0, 0, 1) x-axis (1, 0, 0)
  line (129.6, 109.6) -> (150, 109.6)
  line (150, 109.6) -> (150, 183.4)
  line (150, 183.4) -> (129.6, 183.4)
  line (129.6, 183.4) -> (129.6, 109.6)
extrude "ExtrudedCutout_64" cut finite 0.1 along -normal
sketch for "ExtrudedProtrusion_48" #1 plane through (0, 0, 0) normal (0, 0, 1) x-axis (1, 0, 0)
  line (38.35, 189.15) -> (38.35, 163.85)
  line (38.35, 163.85) -> (95.15, 163.85)
  line (95.15, 163.85) -> (95.15, 189.15)
  line (95.15, 189.15) -> (38.35, 189.15)
sketch for "ExtrudedProtrusion_48" #2 plane through (0, 0, 0) normal (0, 0, 1) x-axis (1, 0, 0)
  line (38.65, 183.85) -> (38.65, 164.15)
  line (38.65, 164.15) -> (94.85, 164.15)
  line (94.85, 164.15) -> (94.85, 183.85)
  line (94.85, 183.85) -> (38.65, 183.85)
extrude "ExtrudedProtrusion_48" add finite 0.1 along +normal
sketch for "ExtrudedCutout_65" plane through (0, 0, 0) normal (0, 0, 1) x-axis (1, 0, 0)
  line (-106.5, 188.5) -> (-106.5, 176.5)
  line (-106.5, 176.5) -> (-83.5, 176.5)
  line (-83.5, 176.5) -> (-83.5, 188.5)
  line (-83.5, 188.5) -> (-106.5, 188.5)
extrude "ExtrudedCutout_65" cut finite 1 along -normal
sketch for "ExtrudedProtrusion_49" plane through (0, 0, 0) normal (0, 0, 1) x-axis (1, 0, 0)
  line (-172.5, 154) -> (-172.5, 133)
  arc centre (-171.5, 133) radius 1 from (-172.5, 133) to (-171.5, 132) ccw
  line (-171.5, 132) -> (-114.5, 132)
  arc centre (-114.5, 133) radius 1 from (-114.5, 132) to (-113.5, 133) ccw
  line (-113.5, 133) -> (-113.5, 154)
  arc centre (-114.5, 154) radius 1 from (-113.5, 154) to (-114.5, 155) ccw
  line (-114.5, 155) -> (-171.5, 155)
  arc centre (-171.5, 154) radius 1 from (-171.5, 155) to (-172.5, 154) ccw
extrude "ExtrudedProtrusion_49" add finite 0.1 along +normal
sketch for "ExtrudedProtrusion_50" plane through (0, 0, 0) normal (0, 0, 1) x-axis (1, 0, 0)
  line (-172.5, 127.5) -> (-172.5, 95)
  line (-172.5, 95) -> (-102.5, 95)
  line (-102.5, 95) -> (-102.5, 127.5)
  line (-102.5, 127.5) -> (-172.5, 127.5)
extrude "ExtrudedProtrusion_50" add finite 0.1 along +normal
sketch for "ExtrudedCutout_66" plane through (0, 0, 0) normal (0, 0, 1) x-axis (1, 0, 0)
  line (-129.15, 79.15) -> (-129.15, 26.85)
  line (-129.15, 26.85) -> (-97.85, 26.85)
  line (-97.85, 26.85) -> (-97.85, 31.85)
  line (-97.85, 31.85) -> (-68.15, 31.85)
  line (-68.15, 31.85) -> (-68.15, 26.85)
  line (-68.15, 26.85) -> (-36.85, 26.85)
  line (-36.85, 26.85) -> (-36.85, 32.15)
  line (-36.85, 32.15) -> (-128.85, 32.15)
  line (-128.85, 32.15) -> (-128.85, 78.85)
  line (-128.85, 78.85) -> (-117.85, 78.85)
  line (-117.85, 78.85) -> (-117.85, 79.15)
  line (-117.85, 79.15) -> (-129.15, 79.15)
extrude "ExtrudedCutout_66" cut finite 0.1 along -normal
